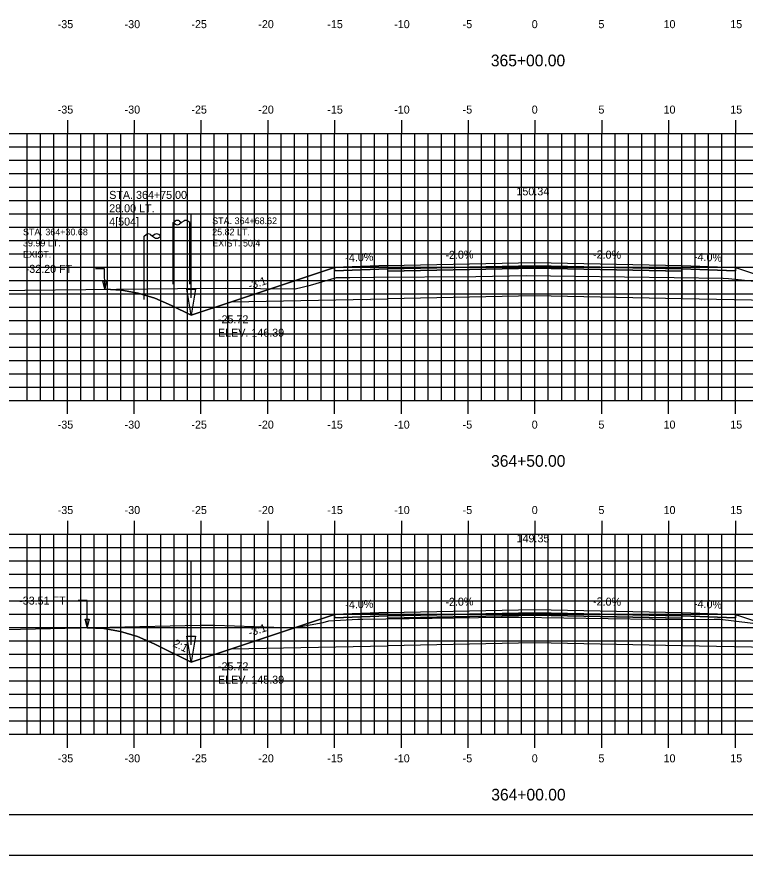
# Model space of a CAD drawing. Extents: x 1147190 to 1147360, y 608981 to 609091.
# Drawn here: x 1147234.2 to 1147288.7, y 608981.3 to 609044.1 of the extents above; entities that cross this region are included whole.
import ezdxf

# ---------------------------------------------------------------- set-up
doc = ezdxf.new("R2010")
doc.units = 0
for name, color, linetype in [('ANNOTATION', 7, 'Continuous'), ('BORDER', 7, 'Continuous'), ('D_Drainage_Ditch_Line', 7, 'Continuous'), ('D_Roadway_Centerline', 7, 'Continuous'), ('D_Roadway_Centerline_Text', 7, 'Continuous'), ('D_Roadway_Edge_Shoulder', 7, 'Continuous'), ('D_Roadway_Edge_TW', 7, 'Continuous'), ('D_Roadway_Pavement', 7, 'Continuous'), ('D_Roadway_SlopeLines', 7, 'Continuous'), ('D_Roadway_SubGrade', 7, 'Continuous'), ('D_Text_Monospaced', 7, 'Continuous'), ('D_Text_Standard', 7, 'Continuous'), ('D_Utilities_Pole_Joint', 7, 'Continuous'), ('H_V ANNOTATION', 7, 'Continuous'), ('MAJOR', 7, 'Continuous'), ('MINOR', 7, 'Continuous'), ('PLOT BOUNDARY', 7, 'Continuous'), ('S_Roadway_Centerline', 7, 'Continuous'), ('S_Utilities_Pole_Power', 7, 'Continuous')]:
    doc.layers.add(name, color=color, linetype=linetype)

msp = doc.modelspace()

# ---------------------------------------------------------------- linework, layer by layer
for points in [[(1147240.739, 609023.683), (1147241.989, 609023.617), (1147243.239, 609023.391), (1147244.489, 609023.006), (1147245.739, 609022.461), (1147247.216, 609021.723), (1147250.216, 609022.723), (1147257.94, 609025.297), (1147257.941, 609025.297), (1147261.941, 609025.457), (1147272.941, 609025.677), (1147283.941, 609025.457), (1147287.941, 609025.297), (1147295.664, 609022.723), (1147298.664, 609021.723), (1147300.098, 609022.439), (1147301.348, 609022.989), (1147302.598, 609023.387), (1147303.848, 609023.634), (1147305.098, 609023.73)], [(1147239.43, 608998.316), (1147240.68, 608998.262), (1147241.93, 608998.046), (1147243.18, 608997.666), (1147244.43, 608997.122), (1147247.216, 608995.729), (1147250.216, 608996.729), (1147257.94, 608999.304), (1147257.941, 608999.304), (1147261.941, 608999.464), (1147272.941, 608999.684), (1147283.941, 608999.464), (1147287.941, 608999.304), (1147295.664, 608996.729), (1147298.664, 608995.729), (1147300.456, 608996.625), (1147301.706, 608997.191), (1147302.956, 608997.64), (1147304.206, 608997.971), (1147305.456, 608998.184)]]:
    msp.add_lwpolyline(points)
at = {"layer": 'BORDER'}
msp.add_lwpolyline([(1147197.941, 608984.335), (1147357.941, 608984.335), (1147357.941, 609089.335), (1147197.941, 609089.335)], close=True, dxfattribs=at)
at = {"layer": 'D_Drainage_Ditch_Line'}
for p, q in [((1147247.216, 609023.035), (1147247.217, 609029.278)), ((1147247.216, 608997.041), (1147247.217, 609003.285))]:
    msp.add_line(p, q, dxfattribs=at)
for points in [[(1147246.888, 609023.691), (1147247.544, 609023.691), (1147247.216, 609021.723)], [(1147246.888, 608997.698), (1147247.544, 608997.698), (1147247.216, 608995.729)]]:
    msp.add_lwpolyline(points, close=True, dxfattribs=at)
at = {"layer": 'D_Roadway_Edge_Shoulder'}
for points in [[(1147261.941, 609025.457), (1147257.941, 609025.297), (1147257.941, 609025.047), (1147261.941, 609025.207)], [(1147283.941, 609025.457), (1147287.941, 609025.297), (1147287.941, 609025.047), (1147283.941, 609025.207)], [(1147261.941, 608999.464), (1147257.941, 608999.304), (1147257.941, 608999.054), (1147261.941, 608999.214)], [(1147283.941, 608999.464), (1147287.941, 608999.304), (1147287.941, 608999.054), (1147283.941, 608999.214)]]:
    msp.add_lwpolyline(points, close=True, dxfattribs=at)
at = {"layer": 'D_Roadway_Edge_TW'}
for points in [[(1147261.941, 609025.207), (1147261.941, 609025.457), (1147272.941, 609025.677), (1147283.941, 609025.457), (1147283.941, 609025.207), (1147272.941, 609025.427)], [(1147261.941, 608999.214), (1147261.941, 608999.464), (1147272.941, 608999.684), (1147283.941, 608999.464), (1147283.941, 608999.214), (1147272.941, 608999.434)]]:
    msp.add_lwpolyline(points, close=True, dxfattribs=at)
at = {"layer": 'D_Roadway_Pavement'}
for points in [[(1147261.941, 609025.04), (1147261.941, 609025.207), (1147272.941, 609025.427), (1147283.941, 609025.207), (1147283.941, 609025.04), (1147272.941, 609025.26)], [(1147261.941, 608999.047), (1147261.941, 608999.214), (1147272.941, 608999.434), (1147283.941, 608999.214), (1147283.941, 608999.047), (1147272.941, 608999.267)]]:
    msp.add_lwpolyline(points, close=True, dxfattribs=at)
at = {"layer": 'D_Roadway_SlopeLines'}
for points in [[(1147247.216, 609021.723), (1147245.739, 609022.461), (1147244.489, 609023.006), (1147243.239, 609023.391), (1147241.989, 609023.617), (1147240.739, 609023.683)], [(1147250.216, 609022.723), (1147247.216, 609021.723)], [(1147247.216, 608995.729), (1147244.43, 608997.122), (1147243.18, 608997.666), (1147241.93, 608998.046), (1147240.68, 608998.262), (1147239.43, 608998.316)], [(1147250.216, 608996.729), (1147247.216, 608995.729)]]:
    msp.add_lwpolyline(points, dxfattribs=at)
at = {"layer": 'D_Roadway_SubGrade'}
for points in [[(1147261.941, 609025.04), (1147261.941, 609025.207), (1147257.941, 609025.047), (1147257.941, 609025.297), (1147257.94, 609025.297), (1147250.216, 609022.723), (1147261.941, 609022.957)], [(1147261.941, 609022.957), (1147261.941, 609025.04), (1147272.941, 609025.26), (1147283.941, 609025.04), (1147283.941, 609022.957), (1147272.941, 609023.177)], [(1147283.941, 609025.04), (1147283.941, 609025.207), (1147287.941, 609025.047), (1147287.941, 609025.297), (1147287.941, 609025.297), (1147295.664, 609022.723), (1147283.941, 609022.957)], [(1147261.941, 608999.047), (1147261.941, 608999.214), (1147257.941, 608999.054), (1147257.941, 608999.304), (1147257.94, 608999.304), (1147250.216, 608996.729), (1147261.941, 608996.964)], [(1147261.941, 608996.964), (1147261.941, 608999.047), (1147272.941, 608999.267), (1147283.941, 608999.047), (1147283.941, 608996.964), (1147272.941, 608997.184)], [(1147283.941, 608999.047), (1147283.941, 608999.214), (1147287.941, 608999.054), (1147287.941, 608999.304), (1147287.941, 608999.304), (1147295.664, 608996.729), (1147283.941, 608996.964)]]:
    msp.add_lwpolyline(points, close=True, dxfattribs=at)
at = {"layer": 'D_Text_Standard'}
for points in [[(1147240.739, 609023.711), (1147240.725, 609025.203), (1147240.045, 609025.203)], [(1147239.43, 608998.372), (1147239.42, 609000.351), (1147238.74, 609000.351)]]:
    msp.add_lwpolyline(points, dxfattribs=at)
for points in [[(1147240.739, 609023.711), (1147240.588, 609024.292), (1147240.879, 609024.295)], [(1147239.43, 608998.372), (1147239.282, 608998.954), (1147239.573, 608998.955)]]:
    msp.add_lwpolyline(points, close=True, dxfattribs=at)
at = {"layer": 'D_Utilities_Pole_Joint'}
for p, q in [((1147243.691, 609027.659), (1147243.847, 609027.769)), ((1147243.691, 609022.901), (1147243.691, 609027.659)), ((1147244.159, 609027.769), (1147244.316, 609027.659)), ((1147244.472, 609027.769), (1147244.316, 609027.659)), ((1147244.316, 609027.659), (1147244.472, 609027.548)), ((1147244.941, 609027.659), (1147244.785, 609027.769)), ((1147244.785, 609027.548), (1147244.941, 609027.659)), ((1147244.941, 609022.901), (1147244.941, 609027.659))]:
    msp.add_line(p, q, dxfattribs=at)
for centre, start, end in [((1147244.003, 609027.548), 90, 125.26439), ((1147244.003, 609027.548), 54.73561, 90), ((1147244.628, 609027.548), 90, 125.26439), ((1147244.628, 609027.769), 234.73561, 270), ((1147244.628, 609027.548), 54.73561, 90), ((1147244.628, 609027.769), 270, 305.26439)]:
    msp.add_arc(centre, 0.271, start, end, dxfattribs=at)
at = {"layer": 'MAJOR'}
for p, q in [((1147237.941, 609036.337), (1147237.941, 609035.335)), ((1147242.941, 609036.337), (1147242.941, 609035.335)), ((1147247.941, 609036.337), (1147247.941, 609035.335)), ((1147252.941, 609036.337), (1147252.941, 609035.335)), ((1147257.941, 609036.337), (1147257.941, 609035.335)), ((1147262.941, 609036.337), (1147262.941, 609035.335)), ((1147267.941, 609036.337), (1147267.941, 609035.335)), ((1147272.941, 609036.337), (1147272.941, 609035.335)), ((1147277.941, 609036.337), (1147277.941, 609035.335)), ((1147282.941, 609036.337), (1147282.941, 609035.335)), ((1147287.941, 609036.337), (1147287.941, 609035.335)), ((1147202.941, 609035.335), (1147342.941, 609035.335)), ((1147202.941, 609035.335), (1147342.941, 609035.335)), ((1147237.941, 609015.335), (1147237.941, 609035.335)), ((1147242.941, 609015.335), (1147242.941, 609035.335)), ((1147247.941, 609015.335), (1147247.941, 609035.335)), ((1147252.941, 609015.335), (1147252.941, 609035.335)), ((1147257.941, 609015.335), (1147257.941, 609035.335)), ((1147262.941, 609015.335), (1147262.941, 609035.335)), ((1147267.941, 609015.335), (1147267.941, 609035.335)), ((1147272.941, 609015.335), (1147272.941, 609035.335)), ((1147277.941, 609015.335), (1147277.941, 609035.335)), ((1147282.941, 609015.335), (1147282.941, 609035.335)), ((1147287.941, 609015.335), (1147287.941, 609035.335)), ((1147202.941, 609030.335), (1147342.941, 609030.335)), ((1147202.941, 609025.335), (1147342.941, 609025.335)), ((1147202.941, 609020.335), (1147342.941, 609020.335)), ((1147202.941, 609015.335), (1147342.941, 609015.335)), ((1147202.941, 609015.335), (1147342.941, 609015.335)), ((1147237.941, 609014.333), (1147237.941, 609015.335)), ((1147242.941, 609014.333), (1147242.941, 609015.335)), ((1147247.941, 609014.333), (1147247.941, 609015.335)), ((1147252.941, 609014.333), (1147252.941, 609015.335)), ((1147257.941, 609014.333), (1147257.941, 609015.335)), ((1147262.941, 609014.333), (1147262.941, 609015.335)), ((1147267.941, 609014.333), (1147267.941, 609015.335)), ((1147272.941, 609014.333), (1147272.941, 609015.335)), ((1147277.941, 609014.333), (1147277.941, 609015.335)), ((1147282.941, 609014.333), (1147282.941, 609015.335)), ((1147287.941, 609014.333), (1147287.941, 609015.335)), ((1147237.941, 609006.337), (1147237.941, 609005.335)), ((1147242.941, 609006.337), (1147242.941, 609005.335)), ((1147247.941, 609006.337), (1147247.941, 609005.335)), ((1147252.941, 609006.337), (1147252.941, 609005.335)), ((1147257.941, 609006.337), (1147257.941, 609005.335)), ((1147262.941, 609006.337), (1147262.941, 609005.335)), ((1147267.941, 609006.337), (1147267.941, 609005.335)), ((1147272.941, 609006.337), (1147272.941, 609005.335)), ((1147277.941, 609006.337), (1147277.941, 609005.335)), ((1147282.941, 609006.337), (1147282.941, 609005.335)), ((1147287.941, 609006.337), (1147287.941, 609005.335)), ((1147202.941, 609005.335), (1147342.941, 609005.335)), ((1147202.941, 609005.335), (1147342.941, 609005.335)), ((1147237.941, 608990.335), (1147237.941, 609005.335)), ((1147242.941, 608990.335), (1147242.941, 609005.335)), ((1147247.941, 608990.335), (1147247.941, 609005.335)), ((1147252.941, 608990.335), (1147252.941, 609005.335)), ((1147257.941, 608990.335), (1147257.941, 609005.335)), ((1147262.941, 608990.335), (1147262.941, 609005.335)), ((1147267.941, 608990.335), (1147267.941, 609005.335)), ((1147272.941, 608990.335), (1147272.941, 609005.335)), ((1147277.941, 608990.335), (1147277.941, 609005.335)), ((1147282.941, 608990.335), (1147282.941, 609005.335)), ((1147287.941, 608990.335), (1147287.941, 609005.335)), ((1147202.941, 609000.335), (1147342.941, 609000.335)), ((1147202.941, 608995.335), (1147342.941, 608995.335)), ((1147202.941, 608990.335), (1147342.941, 608990.335)), ((1147202.941, 608990.335), (1147342.941, 608990.335)), ((1147237.941, 608989.333), (1147237.941, 608990.335)), ((1147242.941, 608989.333), (1147242.941, 608990.335)), ((1147247.941, 608989.333), (1147247.941, 608990.335)), ((1147252.941, 608989.333), (1147252.941, 608990.335)), ((1147257.941, 608989.333), (1147257.941, 608990.335)), ((1147262.941, 608989.333), (1147262.941, 608990.335)), ((1147267.941, 608989.333), (1147267.941, 608990.335)), ((1147272.941, 608989.333), (1147272.941, 608990.335)), ((1147277.941, 608989.333), (1147277.941, 608990.335)), ((1147282.941, 608989.333), (1147282.941, 608990.335)), ((1147287.941, 608989.333), (1147287.941, 608990.335))]:
    msp.add_line(p, q, dxfattribs=at)
at = {"layer": 'MINOR'}
for p, q in [((1147234.941, 609015.335), (1147234.941, 609035.335)), ((1147235.941, 609015.335), (1147235.941, 609035.335)), ((1147236.941, 609015.335), (1147236.941, 609035.335)), ((1147238.941, 609015.335), (1147238.941, 609035.335)), ((1147239.941, 609015.335), (1147239.941, 609035.335)), ((1147240.941, 609015.335), (1147240.941, 609035.335)), ((1147241.941, 609015.335), (1147241.941, 609035.335)), ((1147243.941, 609015.335), (1147243.941, 609035.335)), ((1147244.941, 609015.335), (1147244.941, 609035.335)), ((1147245.941, 609015.335), (1147245.941, 609035.335)), ((1147246.941, 609015.335), (1147246.941, 609035.335)), ((1147248.941, 609015.335), (1147248.941, 609035.335)), ((1147249.941, 609015.335), (1147249.941, 609035.335)), ((1147250.941, 609015.335), (1147250.941, 609035.335)), ((1147251.941, 609015.335), (1147251.941, 609035.335)), ((1147253.941, 609015.335), (1147253.941, 609035.335)), ((1147254.941, 609015.335), (1147254.941, 609035.335)), ((1147255.941, 609015.335), (1147255.941, 609035.335)), ((1147256.941, 609015.335), (1147256.941, 609035.335)), ((1147258.941, 609015.335), (1147258.941, 609035.335)), ((1147259.941, 609015.335), (1147259.941, 609035.335)), ((1147260.941, 609015.335), (1147260.941, 609035.335)), ((1147261.941, 609015.335), (1147261.941, 609035.335)), ((1147263.941, 609015.335), (1147263.941, 609035.335)), ((1147264.941, 609015.335), (1147264.941, 609035.335)), ((1147265.941, 609015.335), (1147265.941, 609035.335)), ((1147266.941, 609015.335), (1147266.941, 609035.335)), ((1147268.941, 609015.335), (1147268.941, 609035.335)), ((1147269.941, 609015.335), (1147269.941, 609035.335)), ((1147270.941, 609015.335), (1147270.941, 609035.335)), ((1147271.941, 609015.335), (1147271.941, 609035.335)), ((1147273.941, 609015.335), (1147273.941, 609035.335)), ((1147274.941, 609015.335), (1147274.941, 609035.335)), ((1147275.941, 609015.335), (1147275.941, 609035.335)), ((1147276.941, 609015.335), (1147276.941, 609035.335)), ((1147278.941, 609015.335), (1147278.941, 609035.335)), ((1147279.941, 609015.335), (1147279.941, 609035.335)), ((1147280.941, 609015.335), (1147280.941, 609035.335)), ((1147281.941, 609015.335), (1147281.941, 609035.335)), ((1147283.941, 609015.335), (1147283.941, 609035.335)), ((1147284.941, 609015.335), (1147284.941, 609035.335)), ((1147285.941, 609015.335), (1147285.941, 609035.335)), ((1147286.941, 609015.335), (1147286.941, 609035.335)), ((1147202.941, 609034.335), (1147342.941, 609034.335)), ((1147202.941, 609033.335), (1147342.941, 609033.335)), ((1147202.941, 609032.335), (1147342.941, 609032.335)), ((1147202.941, 609031.335), (1147342.941, 609031.335)), ((1147202.941, 609029.335), (1147342.941, 609029.335)), ((1147202.941, 609028.335), (1147342.941, 609028.335)), ((1147202.941, 609027.335), (1147342.941, 609027.335)), ((1147202.941, 609026.335), (1147342.941, 609026.335)), ((1147202.941, 609024.335), (1147342.941, 609024.335)), ((1147202.941, 609023.335), (1147342.941, 609023.335)), ((1147202.941, 609022.335), (1147342.941, 609022.335)), ((1147202.941, 609021.335), (1147342.941, 609021.335)), ((1147202.941, 609019.335), (1147342.941, 609019.335)), ((1147202.941, 609018.335), (1147342.941, 609018.335)), ((1147202.941, 609017.335), (1147342.941, 609017.335)), ((1147202.941, 609016.335), (1147342.941, 609016.335)), ((1147234.941, 608990.335), (1147234.941, 609005.335)), ((1147235.941, 608990.335), (1147235.941, 609005.335)), ((1147236.941, 608990.335), (1147236.941, 609005.335)), ((1147238.941, 608990.335), (1147238.941, 609005.335)), ((1147239.941, 608990.335), (1147239.941, 609005.335)), ((1147240.941, 608990.335), (1147240.941, 609005.335)), ((1147241.941, 608990.335), (1147241.941, 609005.335)), ((1147243.941, 608990.335), (1147243.941, 609005.335)), ((1147244.941, 608990.335), (1147244.941, 609005.335)), ((1147245.941, 608990.335), (1147245.941, 609005.335)), ((1147246.941, 608990.335), (1147246.941, 609005.335)), ((1147248.941, 608990.335), (1147248.941, 609005.335)), ((1147249.941, 608990.335), (1147249.941, 609005.335)), ((1147250.941, 608990.335), (1147250.941, 609005.335)), ((1147251.941, 608990.335), (1147251.941, 609005.335)), ((1147253.941, 608990.335), (1147253.941, 609005.335)), ((1147254.941, 608990.335), (1147254.941, 609005.335)), ((1147255.941, 608990.335), (1147255.941, 609005.335)), ((1147256.941, 608990.335), (1147256.941, 609005.335)), ((1147258.941, 608990.335), (1147258.941, 609005.335)), ((1147259.941, 608990.335), (1147259.941, 609005.335)), ((1147260.941, 608990.335), (1147260.941, 609005.335)), ((1147261.941, 608990.335), (1147261.941, 609005.335)), ((1147263.941, 608990.335), (1147263.941, 609005.335)), ((1147264.941, 608990.335), (1147264.941, 609005.335)), ((1147265.941, 608990.335), (1147265.941, 609005.335)), ((1147266.941, 608990.335), (1147266.941, 609005.335)), ((1147268.941, 608990.335), (1147268.941, 609005.335)), ((1147269.941, 608990.335), (1147269.941, 609005.335)), ((1147270.941, 608990.335), (1147270.941, 609005.335)), ((1147271.941, 608990.335), (1147271.941, 609005.335)), ((1147273.941, 608990.335), (1147273.941, 609005.335)), ((1147274.941, 608990.335), (1147274.941, 609005.335)), ((1147275.941, 608990.335), (1147275.941, 609005.335)), ((1147276.941, 608990.335), (1147276.941, 609005.335)), ((1147278.941, 608990.335), (1147278.941, 609005.335)), ((1147279.941, 608990.335), (1147279.941, 609005.335)), ((1147280.941, 608990.335), (1147280.941, 609005.335)), ((1147281.941, 608990.335), (1147281.941, 609005.335)), ((1147283.941, 608990.335), (1147283.941, 609005.335)), ((1147284.941, 608990.335), (1147284.941, 609005.335)), ((1147285.941, 608990.335), (1147285.941, 609005.335)), ((1147286.941, 608990.335), (1147286.941, 609005.335)), ((1147202.941, 609004.335), (1147342.941, 609004.335)), ((1147202.941, 609003.335), (1147342.941, 609003.335)), ((1147202.941, 609002.335), (1147342.941, 609002.335)), ((1147202.941, 609001.335), (1147342.941, 609001.335)), ((1147202.941, 608999.335), (1147342.941, 608999.335)), ((1147202.941, 608998.335), (1147342.941, 608998.335)), ((1147202.941, 608997.335), (1147342.941, 608997.335)), ((1147202.941, 608996.335), (1147342.941, 608996.335)), ((1147202.941, 608994.335), (1147342.941, 608994.335)), ((1147202.941, 608993.335), (1147342.941, 608993.335)), ((1147202.941, 608992.335), (1147342.941, 608992.335)), ((1147202.941, 608991.335), (1147342.941, 608991.335))]:
    msp.add_line(p, q, dxfattribs=at)
at = {"layer": 'PLOT BOUNDARY'}
msp.add_lwpolyline([(1147189.848, 608981.276), (1147359.848, 608981.276), (1147359.848, 609091.276), (1147189.848, 609091.276)], close=True, dxfattribs=at)
at = {"layer": 'S_Roadway_Centerline'}
for points in [[(1147215.532, 609023.394), (1147227.867, 609023.538), (1147246.188, 609023.744), (1147249.793, 609023.75), (1147254.992, 609023.718), (1147256.149, 609023.993), (1147258.083, 609024.547), (1147259.081, 609024.551), (1147260.862, 609024.571), (1147268.511, 609024.64), (1147272.288, 609024.696), (1147275.928, 609024.661), (1147283.359, 609024.561), (1147287.032, 609024.5), (1147287.423, 609024.486), (1147294.421, 609023.747), (1147295.199, 609023.66), (1147295.905, 609023.638), (1147300.455, 609023.669), (1147301.408, 609023.67), (1147307.138, 609023.764), (1147307.507, 609023.763), (1147312.134, 609023.662)], [(1147218.846, 608997.864), (1147241.122, 608998.353), (1147247.885, 608998.514), (1147248.984, 608998.516), (1147254.873, 608998.314), (1147257.094, 608998.713), (1147257.502, 608998.83), (1147259.688, 608998.949), (1147260.064, 608998.953), (1147270.445, 608999.103), (1147271.787, 608999.116), (1147281.744, 608998.963), (1147282.951, 608998.947), (1147286.36, 608998.968), (1147286.809, 608998.965), (1147292.313, 608998.283), (1147293.044, 608998.205), (1147296.983, 608997.246), (1147297.425, 608997.25), (1147298.007, 608997.262), (1147306.226, 608998.28), (1147306.772, 608998.268), (1147312.322, 608998.262)]]:
    msp.add_lwpolyline(points, dxfattribs=at)
at = {"layer": 'S_Utilities_Pole_Power'}
for p, q in [((1147245.866, 609028.675), (1147246.023, 609028.785)), ((1147245.866, 609024.055), (1147245.87, 609028.675)), ((1147246.023, 609028.564), (1147245.866, 609028.675)), ((1147246.335, 609028.785), (1147246.492, 609028.675)), ((1147246.492, 609028.675), (1147246.335, 609028.564)), ((1147246.648, 609028.785), (1147246.492, 609028.675)), ((1147247.116, 609028.675), (1147246.96, 609028.785)), ((1147247.116, 609024.055), (1147247.12, 609028.675))]:
    msp.add_line(p, q, dxfattribs=at)
for centre, start, end in [((1147246.179, 609028.564), 90, 125.26439), ((1147246.179, 609028.564), 54.73561, 90), ((1147246.804, 609028.564), 90, 125.26439), ((1147246.804, 609028.564), 54.73561, 90), ((1147246.179, 609028.785), 234.73561, 270), ((1147246.179, 609028.785), 270, 305.26439)]:
    msp.add_arc(centre, 0.271, start, end, dxfattribs=at)

# ---------------------------------------------------------------- texts
at = {"layer": 'ANNOTATION'}
for s, rotation, p in [('-4.0%', 2.29061, (1147258.757, 609025.73)), ('-2.0%', 1.14576, (1147266.244, 609025.943)), ('-2.0%', 358.85424, (1147277.284, 609025.99)), ('-4.0%', 357.70939, (1147284.837, 609025.822)), ('-3:1', 18.43482, (1147251.595, 609023.636)), ('-4.0%', 2.29061, (1147258.757, 608999.737)), ('-2.0%', 1.14576, (1147266.244, 608999.95)), ('-2.0%', 358.85424, (1147277.284, 608999.997)), ('-4.0%', 357.70939, (1147284.837, 608999.829)), ('-3:1', 18.43482, (1147251.595, 608997.643)), ('2:1', 333.43495, (1147245.79, 608996.96))]:
    msp.add_text(s, height=0.6, rotation=rotation, dxfattribs=at).set_placement(p)
at = {"layer": 'D_Roadway_Centerline'}
for s, p in [('C', (1147272.936, 609025.677)), ('L', (1147272.941, 609025.67)), ('C', (1147272.936, 608999.684)), ('L', (1147272.941, 608999.676))]:
    msp.add_text(s, height=0.0146, dxfattribs=at).set_placement(p)
at = {"layer": 'D_Roadway_Centerline_Text'}
for s, p in [('150.34', (1147271.555, 609030.709)), ('149.35', (1147271.568, 609004.716))]:
    msp.add_text(s, height=0.6, dxfattribs=at).set_placement(p)
at = {"layer": 'D_Text_Monospaced'}
for s, height, p in [('STA. 364+68.62', 0.49998, (1147248.783, 609028.554)), ('STA. 364+30.68', 0.49998, (1147234.621, 609027.717)), ('25.82 LT.', 0.5, (1147248.783, 609027.72)), ('39.99 LT.', 0.5, (1147234.621, 609026.883)), ('EXIST. 50/4', 0.49998, (1147248.783, 609026.88)), ('EXIST. ', 0.5, (1147234.621, 609026.043))]:
    msp.add_text(s, height=height, dxfattribs=at).set_placement(p)
at = {"layer": 'D_Text_Standard'}
for s, p in [('STA. 364+75.00', (1147241.074, 609030.443)), ('28.00 LT.', (1147241.074, 609029.441)), ('4[504] ', (1147241.074, 609028.445)), ('-32.20 FT', (1147234.825, 609024.903)), ('-25.72', (1147249.216, 609021.123)), ('ELEV. 146.39', (1147249.216, 609020.121)), ('-33.51 FT', (1147234.335, 609000.051)), ('-25.72', (1147249.216, 608995.129)), ('ELEV. 145.39', (1147249.216, 608994.127))]:
    msp.add_text(s, height=0.6, dxfattribs=at).set_placement(p)
at = {"layer": 'H_V ANNOTATION'}
for s, height, p in [('-35', 0.6, (1147237.221, 609043.235)), ('-30', 0.6, (1147242.229, 609043.235)), ('-25', 0.6, (1147247.226, 609043.235)), ('-20', 0.6, (1147252.234, 609043.235)), ('-15', 0.6, (1147257.398, 609043.235)), ('-10', 0.6, (1147262.406, 609043.235)), ('-5', 0.6, (1147267.531, 609043.235)), ('0', 0.6, (1147272.7, 609043.235)), ('5', 0.6, (1147277.692, 609043.235)), ('10', 0.6, (1147282.566, 609043.235)), ('15', 0.6, (1147287.558, 609043.235)), ('365+00.00', 0.875, (1147269.64, 609040.378)), ('-35', 0.6, (1147237.221, 609036.835)), ('-30', 0.6, (1147242.229, 609036.835)), ('-25', 0.6, (1147247.226, 609036.835)), ('-20', 0.6, (1147252.234, 609036.835)), ('-15', 0.6, (1147257.398, 609036.835)), ('-10', 0.6, (1147262.406, 609036.835)), ('-5', 0.6, (1147267.531, 609036.835)), ('0', 0.6, (1147272.7, 609036.835)), ('5', 0.6, (1147277.692, 609036.835)), ('10', 0.6, (1147282.566, 609036.835)), ('15', 0.6, (1147287.558, 609036.835)), ('-35', 0.6, (1147237.221, 609013.235)), ('-30', 0.6, (1147242.229, 609013.235)), ('-25', 0.6, (1147247.226, 609013.235)), ('-20', 0.6, (1147252.234, 609013.235)), ('-15', 0.6, (1147257.398, 609013.235)), ('-10', 0.6, (1147262.406, 609013.235)), ('-5', 0.6, (1147267.531, 609013.235)), ('0', 0.6, (1147272.7, 609013.235)), ('5', 0.6, (1147277.692, 609013.235)), ('10', 0.6, (1147282.566, 609013.235)), ('15', 0.6, (1147287.558, 609013.235)), ('364+50.00', 0.875, (1147269.656, 609010.378)), ('-35', 0.6, (1147237.221, 609006.835)), ('-30', 0.6, (1147242.229, 609006.835)), ('-25', 0.6, (1147247.226, 609006.835)), ('-20', 0.6, (1147252.234, 609006.835)), ('-15', 0.6, (1147257.398, 609006.835)), ('-10', 0.6, (1147262.406, 609006.835)), ('-5', 0.6, (1147267.531, 609006.835)), ('0', 0.6, (1147272.7, 609006.835)), ('5', 0.6, (1147277.692, 609006.835)), ('10', 0.6, (1147282.566, 609006.835)), ('15', 0.6, (1147287.558, 609006.835)), ('-35', 0.6, (1147237.221, 608988.235)), ('-30', 0.6, (1147242.229, 608988.235)), ('-25', 0.6, (1147247.226, 608988.235)), ('-20', 0.6, (1147252.234, 608988.235)), ('-15', 0.6, (1147257.398, 608988.235)), ('-10', 0.6, (1147262.406, 608988.235)), ('-5', 0.6, (1147267.531, 608988.235)), ('0', 0.6, (1147272.7, 608988.235)), ('5', 0.6, (1147277.692, 608988.235)), ('10', 0.6, (1147282.566, 608988.235)), ('15', 0.6, (1147287.558, 608988.235)), ('364+00.00', 0.875, (1147269.671, 608985.378))]:
    msp.add_text(s, height=height, dxfattribs=at).set_placement(p)
at = {"layer": 'S_Roadway_Centerline'}
for s, p in [('L', (1147272.279, 609024.689)), ('C', (1147272.282, 609024.696)), ('L', (1147271.779, 608999.108)), ('C', (1147271.782, 608999.116))]:
    msp.add_text(s, height=0.0146, dxfattribs=at).set_placement(p)

doc.saveas('drawing.dxf')
